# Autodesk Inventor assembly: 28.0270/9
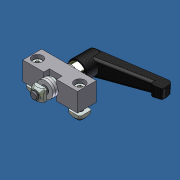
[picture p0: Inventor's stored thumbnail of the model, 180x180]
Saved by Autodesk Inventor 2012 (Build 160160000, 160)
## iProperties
Created: 2011-02
Part Number: 28.0270/9
Document SubType Name: Assembly
Designer: Administrator
Description: SLIDE CLAMPING UNIT 5mm OFFSET
Vendor: S
Mass: 229.022 g
Surface Area: 188.767 cm^2
Volume: 42.7415 cm^3
Density: 5.35829 g/cm^3
Author: Administrator
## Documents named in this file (3)
- C:\Andys Backup Data\ANDY'S INVENTOR\INVENTOR LIBRARIES\PARTS LIBRARY\COMPONENTS LR\28.0270_9 SLIDE CLAMPING UNIT 5mm OFFSET..iam
- C:\Andys Backup Data\ANDY'S INVENTOR\INVENTOR LIBRARIES\PARTS LIBRARY\COMPONENTS LR\SUBCOMPONENTS\28.0270 SLIDE CLAMPING UNIT 5mm OFFSET.iam
- C:\Andys Backup Data\ANDY'S INVENTOR\INVENTOR LIBRARIES\PARTS LIBRARY\FASTENING ELEMENTS\SET SCREWS\21.9841 M4X5 FLAT POINT DIN 913.ipt
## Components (2 placed, 2 different names)
1. 28.0270 SLIDE CLAMPING UNIT 5mm OFFSET:1 [sub-assembly] — Tangent:1, Mate:1
2. 21.9841 SET SCREW M4X5 FLAT POINT DIN 913:1 — Tangent:1, Mate:1
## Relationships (2: Tangent 1, Mate 1)
- Tangent:1: 28.0270 SLIDE CLAMPING UNIT 5mm OFFSET:1 ↔ 21.9841 SET SCREW M4X5 FLAT POINT DIN 913:1
- Mate:1: 28.0270 SLIDE CLAMPING UNIT 5mm OFFSET:1 ↔ 21.9841 SET SCREW M4X5 FLAT POINT DIN 913:1
